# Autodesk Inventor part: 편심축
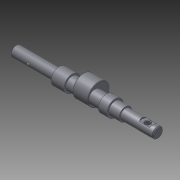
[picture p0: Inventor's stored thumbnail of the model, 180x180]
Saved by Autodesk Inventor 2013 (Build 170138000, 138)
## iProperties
Company: 한국ATC센터
Created: 2015-12
Part Number: 편심축
Document SubType Name: Modeling
Designer: mdu
Density: 7.86 g/cm^3
Mass: 245.851 g
Surface Area: 93.8652 cm^2
Volume: 31.2788 cm^3
Material: 강철, 연강
Author: mdu
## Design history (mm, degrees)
sketch "스케치1"
  geometry: L1 (-83, 0)-(83, 0); L2 (-83, 0)-(-83, 6); L3 (-83, 6)-(-32, 6); L4 (-32, 6)-(-32, 9.5); L5 (-32, 9.5)-(-17, 9.5); L6 (-17, 9.5)-(-17, 7.5); L7 (-17, 7.5)-(45, 7.5); L8 (83, 6)-(83, 0); L9 (33, 7.5)-(33, 9.5); L10 (33, 9.5)-(23, 9.5); L11 (23, 9.5)-(23, 7.5); L12 (45, 7.5)-(45, 6); L13 (45, 6)-(83, 6); 2 further points
  constraints: 26 end point, 6 parallel, 6 perpendicular, 2 point on line, 1 coincident, 1 horizontal, 1 midpoint
  dimensions: "d1" = 12 diameter of L3 L1; "d2" = 15 diameter of L7 L1; "d4" = 15 distance of L4.end L5.end; "d5" = 19 diameter of L5 L1; "d24" = 10 distance of L9.end L10.end; "d25" = 19 diameter of L10 L1; "d27" = 40 distance between parallel lines of L11 L6; "d28" = 51 distance of L2.end L3.end; "d29" = 50 distance between parallel lines of L8 L9; "d41" = 38 distance between parallel lines of L8 L12; "d42" = 12 diameter of L13 L1
revolve "회전1" stored, may be unused: angle "d6" = 90 deg
node "작업 평면1"
sketch "스케치2"
  geometry: C1 r 7.5 at (0, 0) reference; C2 r 12.5 at (0, 4.5); 1 further point
  constraints: 1 centre point, 1 vertical alignment
  dimensions: "d8" = 4.5 distance of point (0, 0) C2.centre; "d9" = 25 diameter of C2
extrude "돌출1" join sketch "스케치2" distance "d10" = 18; taper "d11" = 0 deg
chamfer "모따기1" distance "d12" = 1; stored, may be unused: second distance "d13" = 2, angle "d14" = 45 deg
chamfer "모따기2" distance "d15" = 0.5; stored, may be unused: second distance "d16" = 2, angle "d17" = 45 deg
node "작업 평면2"
sketch "스케치3"
  geometry: L1 (5.5, -2)-(19.5, -2); L2 (19.5, 2)-(5.5, 2); L3 (25.5, 5)-(25.5, -5) reference; A1 r 2 centre (19.5, 0) between (19.5, -2) and (19.5, 2); A2 r 2 centre (5.5, 0) between (5.5, 2) and (5.5, -2); 2 further points
  constraints: 4 end point, 4 point on circle, 4 tangent, 2 centre point, 1 horizontal, 1 horizontal alignment, 1 midpoint, 1 parallel
  dimensions: "d18" = 4 distance edge to line of A1 L3; "d19" = 4 distance between parallel lines of L2 L1; "d20" = 18 dimension on A1 A2
extrude "돌출2" cut sketch "스케치3" distance "d21" = 2.5; taper "d22" = 0 deg
revolve "회전2" stored, may be unused: angle "d26" = 90 deg
node "작업 평면3"
sketch "스케치4"
  geometry: L1 (44, 5)-(44, -5) reference; 2 further points
  constraints: 1 horizontal alignment
  dimensions: "d30" = 12 distance from line of point (32, 0) L1
hole "구멍1" sketch "스케치4" at (32, 0) diameter "d31" = 6; stored, may be unused: countersink angle "d35" = 90 deg, drill point angle "d37" = 118 deg; dims "d32" = 6, "d33" = 14, "d34" = 3, "d36" = 8
node "작업 평면4"
sketch "스케치5"
  geometry: C1 r 3 at (32, 0) reference; C2 r 8 at (32, 0); 2 further points
  constraints: 1 centre point, 1 coincident, 1 other
  dimensions: "d38" = 16 diameter of C2
extrude "돌출3" cut sketch "스케치5" distance "d39" = 3; taper "d40" = 0 deg
sketch "스케치6"
  geometry: L1 (-82, -6)-(-32, -6) reference; L2 (-83, -5)-(-83, 5) reference; L3 (-82, 6)-(-32, 6) reference; L4 (-63, 6)-(-63, -6); L5 (-63, -6)-(-61.5, -6); L6 (-63, -4.5)-(-61.5, -6); L7 (-63, -6)-(-63, -4.5); 2 further points
  constraints: 8 end point, 4 point on line, 2 perpendicular, 1 coincident
  dimensions: "d43" = 20 distance between parallel lines of L4 L2; "d44" = 45 deg angle of L6 L7; "d45" = 3 diameter of L5.end L4
revolve "회전3" stored, may be unused: angle "d46" = 90 deg
node "작업점1"
chamfer "모따기3" distance "d47" = 0.5; stored, may be unused: second distance "d48" = 2, angle "d49" = 45 deg
node "솔리드1"
node "투영된 루프1"
other parameters: "d7" = 8.5
